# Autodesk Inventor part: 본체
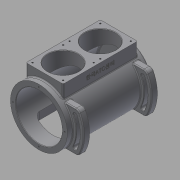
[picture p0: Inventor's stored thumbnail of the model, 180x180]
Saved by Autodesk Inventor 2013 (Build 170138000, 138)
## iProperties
Created: 2016-11
Part Number: 본체
Material: 알루미늄 6061
Document SubType Name: Modeling
Designer: mduedu
Density: 2.71 g/cm^3
Mass: 2488.67 g
Surface Area: 1764.74 cm^2
Volume: 918.329 cm^3
Author: mduedu
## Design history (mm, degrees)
sketch "스케치1"
  geometry: C1 r 65 at (0, 0); 1 further point
  constraints: 1 centre point, 1 coincident
  dimensions: "d119" = 130 diameter of C1
extrude "돌출1" new body sketch "스케치1" distance "d3" = 98; taper "d4" = 0 deg; dims "d132" = 97, "d133" = 0
feature "쉘1" dims "d120" = 12, "d134" = 8
node "작업 평면2"
sketch "스케치13"
  geometry: L1 (42.5, 85)-(-42.5, 85); L2 (-42.5, 85)-(-42.5, -85); L3 (-42.5, -85)-(42.5, -85); L4 (42.5, -85)-(42.5, 85); 2 further points
  constraints: 8 end point, 2 parallel, 1 horizontal, 1 midpoint, 1 perpendicular, 1 vertical alignment
  dimensions: "d122" = 170 distance of L1.end L2.end; "d124" = 85 distance of L2.end L3.end; "d125" = 85 distance from line of point (0, 0) L1 (= 0.5 x d122)
extrude "돌출11" join sketch "스케치13" stored distance "d126" = 10; taper "d127" = 0 deg
sketch "스케치14"
  geometry: L1 (65, 97)-(-65, 97) reference; C1 r 35 at (0, 42.5); 1 further point
  constraints: 1 centre point, 1 vertical alignment
  dimensions: "d128" = 70 diameter of C1; "d129" = 54.5 distance from line of C1.centre L1
extrude "돌출12" cut sketch "스케치14" stored distance "d130" = 10; taper "d131" = 0 deg
sketch "스케치15"
  geometry: C1 r 53 at (0, 0) reference; 1 further point
extrude "돌출13" cut sketch "스케치15" stored distance "d135" = 10; taper "d136" = 0 deg
chamfer "모따기1" distance "d54" = 1; stored, may be unused: second distance "d55" = 2, angle "d56" = 45 deg
sketch "스케치8"
  geometry: C1 r 23 at (0, 0); C2 r 65 at (0, 0) reference; 1 further point
  constraints: 1 centre point, 1 concentric
  dimensions: "d57" = 46 diameter of C1
extrude "돌출8" join sketch "스케치8" distance "d58" = 14; taper "d59" = 0 deg
hole "구멍3" diameter "d62" = 24; stored, may be unused: countersink angle "d66" = 90 deg, drill point angle "d68" = 0 deg; dims "d63" = 6, "d64" = 28, "d65" = 8, "d67" = 14, "d169" = 10, "d170" = 10
fillet "모깎기11" dims "d69" = 3
fillet "모깎기12" dims "d70" = 3
fillet "모깎기13" dims "d71" = 0.3
chamfer "모따기2" distance "d72" = 1; stored, may be unused: second distance "d73" = 2, angle "d74" = 45 deg
node "작업 평면3"
sketch "스케치16"
  geometry: L1 (-42.5, -80)-(47.5, -80); L2 (-42.5, -80)-(21.14, -16.36); L3 (-42.5, -80)-(21.14, -143.64); L4 (3.462, -34.038)-(34.879, -34.038); L5 (3.462, -125.962)-(34.879, -125.962); A1 r 65 centre (-42.5, -80) between (3.462, -34.038) and (3.462, -125.962) reference; A2 r 90 centre (-42.5, -80) between (34.879, -125.962) and (34.879, -34.038); A3 r 90 centre (-42.5, -80) between (34.879, -34.038) and (34.879, -125.962); A4 r 65 centre (-42.5, -80) between (3.462, -125.962) and (3.462, -34.038); 1 further point
  constraints: 11 point on circle, 10 end point, 3 centre point, 2 parallel, 2 point on line, 1 coincident, 1 horizontal
  dimensions: "d140" = 45 deg angle of L3 L1; "d141" = 45 deg angle of L2 L1; "d142" = 25 radial gap between concentric circles of A1 A2
extrude "돌출14" join sketch "스케치16" distance "d143" = 15; taper "d144" = 0 deg
sketch "스케치17"
  geometry: L1 (-42.5, -80)-(34.414, -80); L2 (-42.5, -80)-(27.208, -47.495); L3 (-42.5, -80)-(27.208, -112.505); L4 (34.879, -34.038)-(3.462, -34.038) reference; L5 (3.462, -125.962)-(34.879, -125.962) reference; A1 r 65 centre (-42.5, -80) between (3.462, -34.038) and (3.462, -125.962) reference; A2 r 76.914 centre (-42.5, -80) between (19.17, -125.962) and (19.17, -34.038); A3 r 4 centre (27.208, -47.495) between (23.582, -49.185) and (30.833, -45.804); A4 r 4 centre (27.208, -112.505) between (30.833, -114.196) and (23.582, -110.815); A5 r 80.914 centre (-42.5, -80) between (30.833, -114.196) and (30.833, -45.804); A6 r 72.914 centre (-42.5, -80) between (23.582, -110.815) and (23.582, -49.185); 1 further point
  constraints: 13 point on circle, 6 end point, 5 centre point, 5 coincident, 3 midpoint, 2 point on line, 1 equal radius, 1 horizontal
  dimensions: "d145" = 25 deg angle of L1 L3; "d146" = 25 deg angle of L2 L1; "d147" = 8 diameter of A3
extrude "돌출15" cut sketch "스케치17" stored distance "d150" = 15; taper "d151" = 0 deg
fillet "모깎기17" dims "d152" = 10
fillet "모깎기18" dims "d153" = 2
fillet "모깎기19" dims "d154" = 2
chamfer "모따기4" distance "d155" = 1; stored, may be unused: second distance "d156" = 2, angle "d157" = 45 deg
fillet "모깎기20" dims "d159" = 3
fillet "모깎기21" dims "d160" = 3
fillet "모깎기22" dims "d161" = 3
node "작업 평면4"
sketch "스케치18"
  geometry: L1 (-42.5, 65)-(42.5, 65); L2 (42.5, 65)-(42.5, -65); L3 (42.5, -65)-(-42.5, -65); L4 (-42.5, -65)-(-42.5, 65); 2 further points
  constraints: 8 end point, 2 parallel, 1 horizontal, 1 midpoint, 1 perpendicular, 1 vertical alignment
  dimensions: "d162" = 130 distance of L1.end L2.end; "d164" = 85 distance of L2.end L3.end; "d165" = 65 distance from line of point (0, 0) L1 (= 0.5 x d162)
extrude "돌출16" cut sketch "스케치18" stored distance "d166" = 15; taper "d167" = 0 deg
fillet "모깎기23" dims "d168" = 10
fillet "모깎기24" dims "d173" = 3
sketch "스케치19"
  geometry: 4 further points
  constraints: 4 other
hole "구멍6" sketch "스케치19" at (0, -59), (59, 0), (-59, 0), (0, 59) diameter "d174" = 3.242; stored, may be unused: countersink angle "d178" = 90 deg, drill point angle "d180" = 120 deg; dims "d175" = 7, "d176" = 4, "d177" = 2, "d179" = 9
sketch "스케치20"
  geometry: L1 (35, -77.5)-(-35, -77.5); L2 (-35, -77.5)-(-35, -7.5); L3 (-35, -7.5)-(35, -7.5); L4 (35, -7.5)-(35, -77.5); L5 (35, -77.5)-(-35, -7.5); L6 (-35, -77.5)-(35, -7.5); C1 r 36 at (0, -42.5) reference; 5 further points
  constraints: 12 end point, 4 coincident, 2 midpoint, 2 parallel, 1 horizontal, 1 perpendicular
  dimensions: "d181" = 70 distance of L2.end L3.end; "d182" = 70 distance of L1.end L2.end
hole "구멍7" sketch "스케치20" at (-35, -77.5), (-35, -7.5), (35, -7.5), (35, -77.5) diameter "d183" = 3.242; stored, may be unused: countersink angle "d187" = 90 deg, drill point angle "d189" = 118 deg; dims "d184" = 7, "d185" = 4, "d186" = 2, "d188" = 9
sketch "스케치21"
  geometry: L1 (164, 0)-(0, 0) reference; L2 (-3, 0)-(-3, -24.649) reference; 3 further points
  constraints: 1 midpoint, 1 vertical alignment, 1 other
  dimensions: "d190" = 15 distance from line of point (82, -15) L1; "d191" = 85 distance from line of point (82, 0) L2 (derived)
feature "엠보싱2" sketch "스케치21" dims "d3" = 98, "d4" = 0, "d119" = 130, "d132" = 97, "d133" = 0, "d192" = 0.5, "d193" = 0
node "솔리드1"
mirror "대칭5"
mirror "대칭6"
mirror "대칭7"
